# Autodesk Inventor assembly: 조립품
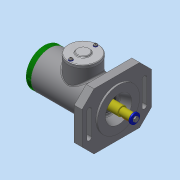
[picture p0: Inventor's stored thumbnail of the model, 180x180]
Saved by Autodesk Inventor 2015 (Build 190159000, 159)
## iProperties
Created: 2017-10
Part Number: 조립품
Document SubType Name: Assembly
Designer: Administrator
Author: Administrator
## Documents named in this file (20)
- C:\Users\Administrator\Desktop\471007V1012\조립품.iam
- C:\Users\Administrator\Desktop\471007V1012\본체.ipt
- C:\Users\Administrator\Desktop\471007V1012\V-벨트풀리.ipt
- C:\Users\Administrator\Desktop\471007V1012\너트 M10.ipt
- C:\Users\Administrator\Desktop\471007V1012\멈춤링 15 x 1.ipt
- C:\Users\Administrator\Desktop\471007V1012\멈춤링 35x1.6.ipt
- C:\Users\Administrator\Desktop\471007V1012\베어링 15 x 35 x 11.ipt
- C:\Users\Administrator\Desktop\471007V1012\볼트 M4 x 10.ipt
- C:\Users\Administrator\Desktop\471007V1012\부시1.ipt
- C:\Users\Administrator\Desktop\471007V1012\부시2.ipt
- C:\Users\Administrator\Desktop\471007V1012\사이드 커버.ipt
- 사이드 커버.ipt
- C:\Users\Administrator\Desktop\471007V1012\십자볼트 M3 x 10.ipt
- C:\Users\Administrator\Desktop\471007V1012\오일 실 15 25 7.ipt
- C:\Users\Administrator\Desktop\471007V1012\와셔 3x6.ipt
- C:\Users\Administrator\Desktop\471007V1012\와셔 4x16.ipt
- C:\Users\Administrator\Desktop\471007V1012\와셔 10x21.ipt
- C:\Users\Administrator\Desktop\471007V1012\축.ipt
- C:\Users\Administrator\Desktop\471007V1012\키 4 x 4 x 18.ipt
- C:\Users\Administrator\Desktop\471007V1012\탑 커버.ipt
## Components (2 placed, 2 different names)
1. V-벨트풀리:1 — 각도:1
2. ISO 4017 M4 x 10:1
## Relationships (1: Angle 1)
- 각도:1 [Angle]: V-벨트풀리:1
